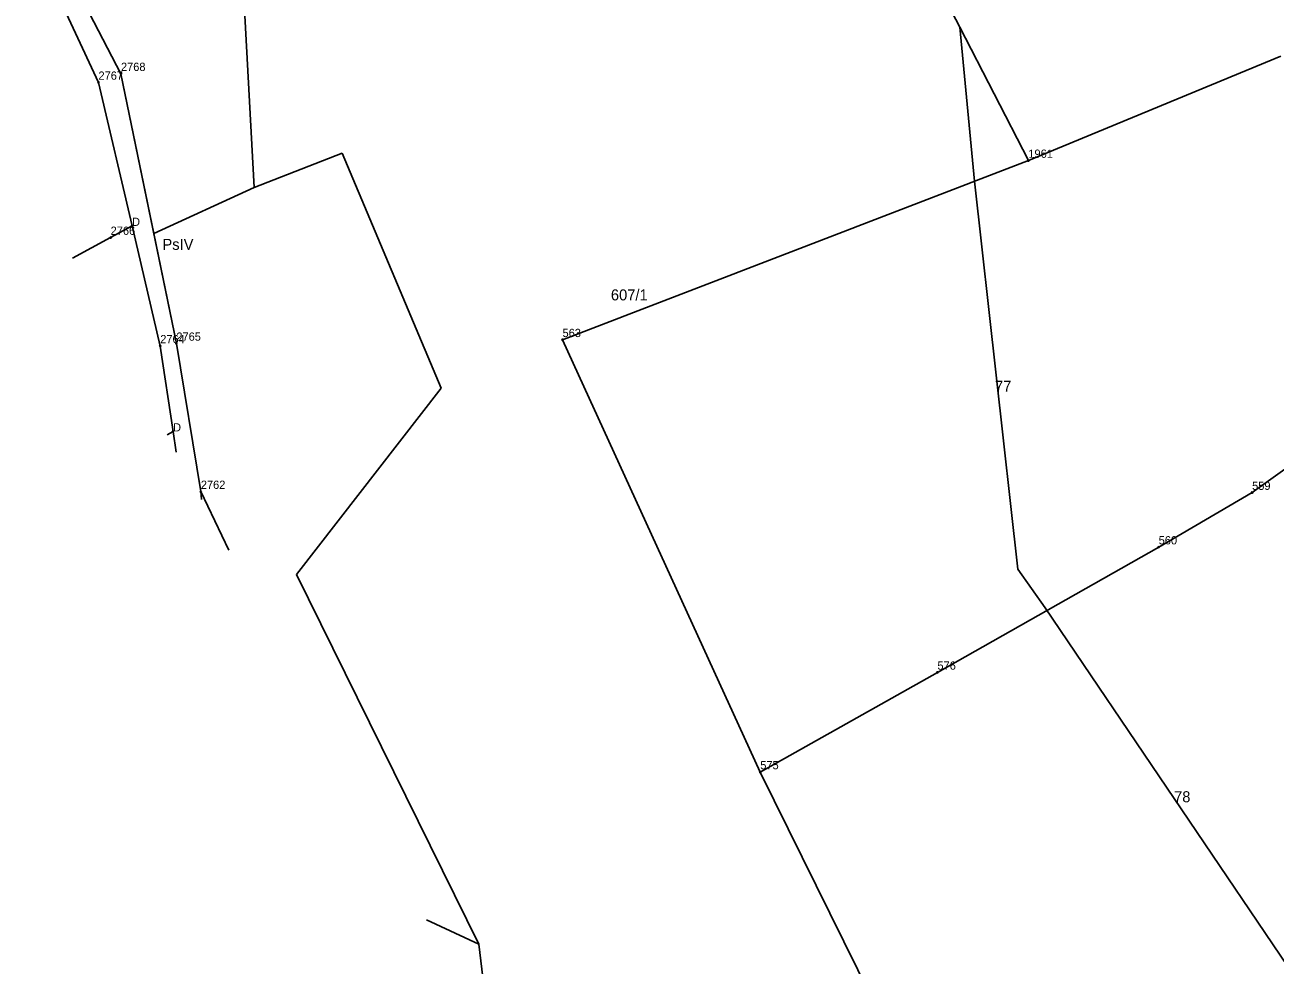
# Model space of a CAD drawing. Extents: x 7467189 to 7469366, y 5491487 to 5492734.
# Drawn here: x 7467316.3 to 7467486.9, y 5492251.8 to 5492380.2 of the extents above; entities that cross this region are included whole.
import ezdxf

# ---------------------------------------------------------------- set-up
doc = ezdxf.new("R2010")
doc.units = 0
for name, color, linetype in [('203-punkt graniczny', 7, 'Continuous'), ('203-punkt graniczny-Atr103', 7, 'Continuous'), ('209-oznaczenie konturu klasyfikacyjnego', 7, 'Continuous'), ('210-oznaczenie konturu użytku gruntowego', 7, 'Continuous'), ('211-numer działki ewidencyjnej', 7, 'Continuous'), ('217-kontur klasyfikacyjny', 7, 'Continuous'), ('218-kontur użytku gruntowego', 7, 'Continuous'), ('219-działka ewidencyjna', 7, 'Continuous')]:
    doc.layers.add(name, color=color, linetype=linetype)

# ---------------------------------------------------------------- blocks, each defined once
blk = doc.blocks.new('203')
blk.add_circle((0, 0), 0.09)

msp = doc.modelspace()

# ---------------------------------------------------------------- linework, layer by layer
at = {"layer": '217-kontur klasyfikacyjny'}
for points in [[(7467342.11, 5492458.65), (7467347.55, 5492357.96)], [(7467426.37, 5492413.56), (7467443.88, 5492379.85)], [(7467318.34, 5492394.72), (7467329.37, 5492373.5)], [(7467443.88, 5492379.85), (7467453.22, 5492361.64)], [(7467443.88, 5492379.85), (7467445.86, 5492358.81)], [(7467453.22, 5492361.64), (7467487.69, 5492375.9)], [(7467329.37, 5492373.5), (7467333.85, 5492351.67)], [(7467359.57, 5492362.64), (7467347.55, 5492357.96)], [(7467373.07, 5492330.56), (7467359.57, 5492362.64)], [(7467445.86, 5492358.81), (7467451.8, 5492305.83)], [(7467347.55, 5492357.96), (7467333.85, 5492351.67)], [(7467333.85, 5492351.67), (7467336.93, 5492336.66)], [(7467336.93, 5492336.66), (7467340.27, 5492316.43)], [(7467353.35, 5492305.11), (7467373.07, 5492330.56)], [(7467340.27, 5492316.43), (7467340.36, 5492315.37)], [(7467451.8, 5492305.83), (7467455.52, 5492300.57)], [(7467378.22, 5492254.64), (7467353.35, 5492305.11)], [(7467455.52, 5492300.57), (7467490.71, 5492248.48)], [(7467371.07, 5492257.95), (7467378.22, 5492254.64)], [(7467378.22, 5492254.64), (7467379.75, 5492241.74)]]:
    msp.add_lwpolyline(points, dxfattribs=at)
at = {"layer": '218-kontur użytku gruntowego'}
for points in [[(7467426.37, 5492413.56), (7467443.88, 5492379.85)], [(7467318.34, 5492394.72), (7467329.37, 5492373.5)], [(7467326.3, 5492372.31), (7467316.27, 5492393.9)], [(7467443.88, 5492379.85), (7467453.22, 5492361.64)], [(7467453.22, 5492361.64), (7467487.69, 5492375.9)], [(7467330.89, 5492352.72), (7467326.3, 5492372.31)], [(7467329.37, 5492373.5), (7467333.85, 5492351.67)], [(7467359.57, 5492362.64), (7467347.55, 5492357.96)], [(7467373.07, 5492330.56), (7467359.57, 5492362.64)], [(7467347.55, 5492357.96), (7467333.85, 5492351.67)], [(7467334.73, 5492336.32), (7467330.89, 5492352.72)], [(7467333.85, 5492351.67), (7467336.93, 5492336.66)], [(7467336.49, 5492324.65), (7467334.73, 5492336.32)], [(7467336.93, 5492336.66), (7467340.27, 5492316.43)], [(7467353.35, 5492305.11), (7467373.07, 5492330.56)], [(7467336.92, 5492321.81), (7467336.49, 5492324.65)], [(7467340.27, 5492316.43), (7467340.36, 5492315.37)], [(7467378.22, 5492254.64), (7467353.35, 5492305.11)], [(7467378.22, 5492254.64), (7467371.07, 5492257.95)], [(7467379.75, 5492241.74), (7467378.22, 5492254.64)]]:
    msp.add_lwpolyline(points, dxfattribs=at)
at = {"layer": '219-działka ewidencyjna'}
for points in [[(7467318.34, 5492394.72), (7467329.37, 5492373.5)], [(7467316.27, 5492393.9), (7467326.3, 5492372.31)], [(7467453.22, 5492361.64), (7467487.69, 5492375.9)], [(7467330.89, 5492352.72), (7467326.3, 5492372.31)], [(7467329.37, 5492373.5), (7467336.93, 5492336.66)], [(7467389.64, 5492337.17), (7467453.22, 5492361.64)], [(7467330.89, 5492352.72), (7467327.96, 5492351.13)], [(7467330.89, 5492352.72), (7467334.73, 5492336.32)], [(7467322.75, 5492348.3), (7467327.96, 5492351.13)], [(7467336.49, 5492324.65), (7467334.73, 5492336.32)], [(7467336.93, 5492336.66), (7467340.27, 5492316.43)], [(7467389.64, 5492337.17), (7467416.63, 5492278.14)], [(7467336.49, 5492324.65), (7467335.66, 5492324.17)], [(7467336.49, 5492324.65), (7467336.92, 5492321.81)], [(7467483.76, 5492316.3), (7467489.48, 5492320.41)], [(7467340.27, 5492316.43), (7467340.36, 5492315.37)], [(7467344.08, 5492308.42), (7467340.27, 5492316.43)], [(7467471.01, 5492308.85), (7467483.76, 5492316.3)], [(7467440.81, 5492291.75), (7467471.01, 5492308.85)], [(7467416.63, 5492278.14), (7467440.81, 5492291.75)], [(7467416.63, 5492278.14), (7467448.99, 5492212.54)]]:
    msp.add_lwpolyline(points, dxfattribs=at)

# ---------------------------------------------------------------- block references
at = {"layer": '203-punkt graniczny'}
for p in [(7467326.3, 5492372.31), (7467329.37, 5492373.5), (7467453.22, 5492361.64), (7467330.89, 5492352.72), (7467327.96, 5492351.13), (7467334.73, 5492336.32), (7467336.93, 5492336.66), (7467389.64, 5492337.17), (7467336.49, 5492324.65), (7467340.27, 5492316.43), (7467483.76, 5492316.3), (7467471.01, 5492308.85), (7467440.81, 5492291.75), (7467416.63, 5492278.14)]:
    msp.add_blockref('203', p, dxfattribs=at)

# ---------------------------------------------------------------- texts
at = {"layer": '203-punkt graniczny-Atr103'}
for s, height, p in [('2767', 1.125, (7467326.3, 5492372.68)), ('2768', 1.125, (7467329.37, 5492373.88)), ('1961', 1.125, (7467453.22, 5492362.02)), ('D', 1.12, (7467330.89, 5492352.72)), ('2766', 1.125, (7467327.96, 5492351.5)), ('2765', 1.125, (7467336.93, 5492337.04)), ('563', 1.125, (7467389.64, 5492337.54)), ('2764', 1.125, (7467334.73, 5492336.7)), ('D', 1.12, (7467336.49, 5492324.65)), ('2762', 1.125, (7467340.27, 5492316.81)), ('559', 1.125, (7467483.76, 5492316.67)), ('560', 1.125, (7467471.01, 5492309.23)), ('576', 1.125, (7467440.81, 5492292.12)), ('575', 1.125, (7467416.63, 5492278.52))]:
    msp.add_text(s, height=height, dxfattribs=at).set_placement(p)
at = {"layer": '209-oznaczenie konturu klasyfikacyjnego'}
msp.add_text('PsIV', height=1.5, dxfattribs=at).set_placement((7467335.03, 5492349.45))
at = {"layer": '210-oznaczenie konturu użytku gruntowego'}
msp.add_text('Ps', height=1.5, dxfattribs=at).set_placement((7467335.03, 5492349.45))
at = {"layer": '211-numer działki ewidencyjnej'}
for s, p in [('607/1', (7467396.24, 5492342.55)), ('77', (7467448.67, 5492330.08)), ('78', (7467473.11, 5492274.02))]:
    msp.add_text(s, height=1.5, dxfattribs=at).set_placement(p)

doc.saveas('drawing.dxf')
